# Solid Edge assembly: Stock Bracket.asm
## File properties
Author: CADCIM
Template: ansi assembly.asm
Last saved by: CADCIM
Revision: 8
Application: Solid Edge
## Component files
support_roller_bracket.par
stock_support_roller.par
adjusting_nut_handle.par
adjusting_screw_guide.par
Stock_support_base.par
thrust_bearing.par
adjusting_screw_nut.par
support_adjusting_screw.par
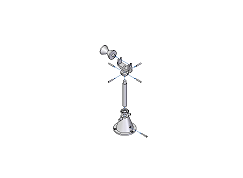
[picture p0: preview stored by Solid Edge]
